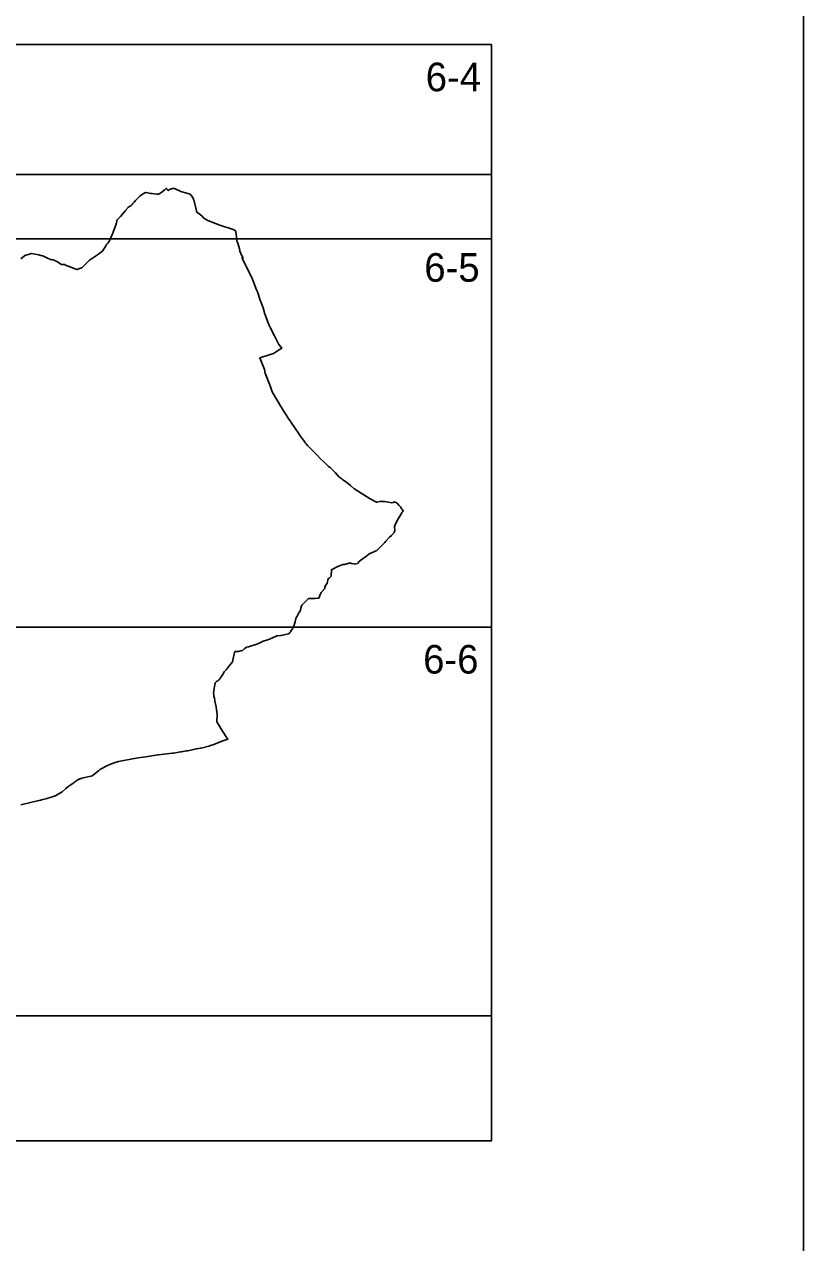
# Model space of a CAD drawing. Extents: x -447352 to -425530, y -1135906 to -1125104.
# Drawn here: x -438259.4 to -438008.8, y -1126663.9 to -1126271.9 of the extents above; entities that cross this region are included whole.
import ezdxf

# ---------------------------------------------------------------- set-up
doc = ezdxf.new("R2010")
doc.units = 0
for name, color, linetype in [('Vrstva 1', 7, 'Continuous'), ('Vrstva 10', 7, 'Continuous'), ('Vrstva 4', 7, 'Continuous')]:
    doc.layers.add(name, color=color, linetype=linetype)

msp = doc.modelspace()

# ---------------------------------------------------------------- linework, layer by layer
at = {"layer": 'Vrstva 1'}
msp.add_lwpolyline([(-439493.8, -1126016.81), (-439493.8, -1127066.81), (-438008.8, -1127066.81), (-438008.8, -1126016.81)], close=True, dxfattribs=at)
msp.add_lwpolyline([(-438260.51, -1126523.09), (-438256.97, -1126522.22), (-438254.2, -1126521.55), (-438253.53, -1126521.34), (-438252.04, -1126520.98), (-438251.83, -1126520.92), (-438250.4, -1126520.53), (-438249.8, -1126520.27), (-438249.58, -1126520.17), (-438249.42, -1126520.11), (-438248.6, -1126519.66), (-438248.54, -1126519.62), (-438247.23, -1126518.84), (-438246.08, -1126517.79), (-438245.43, -1126517.29), (-438245.3, -1126517.18), (-438245.28, -1126517.17), (-438245.12, -1126517.04), (-438244.97, -1126516.94), (-438244.17, -1126516.38), (-438244.11, -1126516.34), (-438244.04, -1126516.29), (-438243.53, -1126515.94), (-438243.16, -1126515.68), (-438242.5, -1126515.22), (-438241.91, -1126514.81), (-438241.75, -1126514.84), (-438241.74, -1126514.84), (-438241.72, -1126514.82), (-438240.99, -1126514.43), (-438238.03, -1126513.85), (-438237.61, -1126513.7), (-438235.58, -1126512.07), (-438235.11, -1126511.73), (-438235.08, -1126511.71), (-438234.72, -1126511.45), (-438234.54, -1126511.33), (-438233.15, -1126510.63), (-438231.74, -1126509.99), (-438231.44, -1126509.84), (-438230.18, -1126509.38), (-438229.18, -1126509.13), (-438223.47, -1126508.07), (-438222.05, -1126507.81), (-438220.34, -1126507.56), (-438216.47, -1126506.99), (-438216.23, -1126506.96), (-438211.93, -1126506.44), (-438211.4, -1126506.38), (-438209.25, -1126506.02), (-438208.93, -1126505.97), (-438207.27, -1126505.7), (-438206.87, -1126505.63), (-438205.46, -1126505.34), (-438204.17, -1126505.07), (-438203.96, -1126505.03), (-438202.79, -1126504.8), (-438202.12, -1126504.67), (-438202.1, -1126504.67), (-438201.19, -1126504.46), (-438201.12, -1126504.44), (-438200.47, -1126504.28), (-438200.12, -1126504.17), (-438199.23, -1126503.88), (-438198.79, -1126503.73), (-438198.14, -1126503.49), (-438198.02, -1126503.45), (-438196.93, -1126502.96), (-438196.93, -1126502.96), (-438196.81, -1126502.92), (-438196.16, -1126502.69), (-438196.07, -1126502.66), (-438195.64, -1126502.5), (-438193.98, -1126501.92), (-438194, -1126501.87), (-438194.11, -1126501.7), (-438194.27, -1126501.47), (-438194.49, -1126501.15), (-438196.19, -1126498.51), (-438196.4, -1126498.16), (-438196.57, -1126497.89), (-438197.01, -1126497.18), (-438197.54, -1126496.33), (-438197.38, -1126493.97), (-438197.37, -1126493.88), (-438197.76, -1126491.58), (-438197.76, -1126491.56), (-438197.77, -1126491.54), (-438197.77, -1126491.54), (-438197.77, -1126491.51), (-438198.18, -1126489.68), (-438198.19, -1126489.49), (-438198.25, -1126488.69), (-438198.35, -1126488.41), (-438198.36, -1126488.39), (-438198.47, -1126488.17), (-438198.51, -1126488.09), (-438198.52, -1126487.71), (-438198.55, -1126487.01), (-438198.5, -1126486.52), (-438198.5, -1126486.5), (-438198.41, -1126485.64), (-438198.39, -1126485.53), (-438198.1, -1126483.89), (-438198.02, -1126483.81), (-438197.72, -1126483.47), (-438197.66, -1126483.4), (-438197.4, -1126483.28), (-438197.34, -1126483.22), (-438197.08, -1126483.02), (-438196.85, -1126482.84), (-438196.64, -1126482.68), (-438196.58, -1126482.64), (-438196.5, -1126482.51), (-438196.42, -1126482.39), (-438196.31, -1126482.22), (-438196.09, -1126481.89), (-438195.67, -1126481.24), (-438195.54, -1126480.99), (-438195.53, -1126480.98), (-438195.39, -1126480.69), (-438195.34, -1126480.6), (-438195.16, -1126480.27), (-438195.02, -1126480.12), (-438194.72, -1126479.81), (-438194.55, -1126479.63), (-438194.27, -1126479.28), (-438194.14, -1126479.11), (-438193.45, -1126478.26), (-438192.79, -1126477.45), (-438192.5, -1126477.09), (-438192.26, -1126475.92), (-438192.2, -1126475.69), (-438192.13, -1126475.41), (-438191.81, -1126474.1), (-438191.73, -1126473.82), (-438191.73, -1126473.79), (-438191.71, -1126473.74), (-438191.55, -1126473.73), (-438191.53, -1126473.73), (-438191.29, -1126473.73), (-438190.6, -1126473.71), (-438190.59, -1126473.71), (-438190.56, -1126473.71), (-438189.88, -1126473.53), (-438189.68, -1126473.47), (-438189.26, -1126473.36), (-438189.24, -1126473.35), (-438189.18, -1126473.29), (-438188.88, -1126473.01), (-438188.76, -1126472.93), (-438188.42, -1126472.67), (-438188, -1126472.35), (-438187.93, -1126472.33), (-438187.37, -1126472.17), (-438184.67, -1126471.41), (-438184.08, -1126471.14), (-438183.75, -1126470.98), (-438183.7, -1126470.96), (-438183.6, -1126470.91), (-438183.24, -1126470.73), (-438183.19, -1126470.71), (-438183.16, -1126470.69), (-438183.15, -1126470.69), (-438183.12, -1126470.67), (-438182.81, -1126470.52), (-438182.75, -1126470.48), (-438182.64, -1126470.43), (-438181.56, -1126470.1), (-438181.13, -1126469.92), (-438180.61, -1126469.7), (-438179.6, -1126469.29), (-438178.18, -1126468.66), (-438178.04, -1126468.65), (-438176.91, -1126468.6), (-438174.51, -1126468.04), (-438173.98, -1126467.64), (-438173.91, -1126467.52), (-438173.82, -1126467.34), (-438173.56, -1126466.83), (-438173.21, -1126466.4), (-438173.19, -1126466.37), (-438172.98, -1126466.08), (-438172.87, -1126465.92), (-438172.86, -1126465.91), (-438172.32, -1126464.13), (-438172.31, -1126464.1), (-438172.11, -1126463.15), (-438171.85, -1126462.69), (-438171.66, -1126462.36), (-438171.11, -1126461.24), (-438170.73, -1126460.73), (-438170.7, -1126460.6), (-438170.63, -1126460.3), (-438170.6, -1126460.16), (-438170.54, -1126459.91), (-438170.52, -1126459.81), (-438170.2, -1126458.8), (-438170.19, -1126458.79), (-438169.9, -1126458.51), (-438169.24, -1126457.88), (-438169.19, -1126457.83), (-438168.72, -1126457.35), (-438168.46, -1126457.09), (-438168.36, -1126456.98), (-438167.99, -1126456.66), (-438167.95, -1126456.66), (-438167.94, -1126456.66), (-438167.53, -1126456.65), (-438167.36, -1126456.66), (-438166.73, -1126456.68), (-438166.02, -1126456.68), (-438165.05, -1126456.59), (-438165.02, -1126456.59), (-438164.77, -1126456.56), (-438164.55, -1126456.2), (-438164.5, -1126456.07), (-438164.48, -1126456.02), (-438164.46, -1126455.96), (-438164.1, -1126454.94), (-438163.96, -1126454.77), (-438163.86, -1126454.66), (-438163.82, -1126454.62), (-438163.76, -1126454.54), (-438163.64, -1126454.41), (-438163.37, -1126454.09), (-438163.28, -1126453.99), (-438163.18, -1126453.87), (-438162.84, -1126453.48), (-438162.77, -1126453.09), (-438162.71, -1126452.78), (-438162.64, -1126452.65), (-438162.09, -1126451.73), (-438161.98, -1126451.34), (-438161.79, -1126450.64), (-438161.67, -1126450.35), (-438161.38, -1126450.08), (-438160.83, -1126449.57), (-438160.76, -1126449.51), (-438160.66, -1126447.4), (-438159.64, -1126446.91), (-438159.24, -1126446.7), (-438158.99, -1126446.57), (-438158.7, -1126446.41), (-438158.48, -1126446.33), (-438158.14, -1126446.2), (-438158.09, -1126446.19), (-438157, -1126445.78), (-438156.99, -1126445.78), (-438156.5, -1126445.72), (-438156.42, -1126445.7), (-438155.39, -1126445.44), (-438155.24, -1126445.4), (-438155.15, -1126445.37), (-438154.98, -1126445.32), (-438154.45, -1126445.15), (-438154.45, -1126445.15), (-438154.44, -1126445.16), (-438154.44, -1126445.16), (-438154.41, -1126445.22), (-438154.28, -1126445.44), (-438153.4, -1126445.54), (-438153.2, -1126445.56), (-438152.84, -1126445.6), (-438152.75, -1126445.56), (-438152.32, -1126445.38), (-438151.67, -1126444.67), (-438150.03, -1126443.51), (-438149.94, -1126443.44), (-438149.77, -1126443.33), (-438149.26, -1126442.91), (-438148.51, -1126442.31), (-438147.24, -1126441.74), (-438146.62, -1126441.47), (-438146.08, -1126441.23), (-438146.02, -1126441.2), (-438144.37, -1126439.53), (-438143.53, -1126438.64), (-438143.17, -1126438.26), (-438141.98, -1126436.9), (-438141.38, -1126436.44), (-438141.33, -1126436.4), (-438140.49, -1126435.39), (-438140.29, -1126434.82), (-438140.38, -1126433.49), (-438140.16, -1126433), (-438139.52, -1126431.55), (-438138.06, -1126429.07), (-438138.03, -1126429.02), (-438138.03, -1126429.02), (-438138.01, -1126428.99), (-438137.98, -1126428.95), (-438137.83, -1126428.76), (-438137.57, -1126428.42), (-438137.83, -1126428.12), (-438137.97, -1126427.9), (-438138.44, -1126427.16), (-438138.64, -1126426.97), (-438138.79, -1126426.81), (-438138.98, -1126426.61), (-438139.56, -1126426.04), (-438140.41, -1126425.57), (-438140.86, -1126425.75), (-438141.19, -1126425.87), (-438142.94, -1126425.6), (-438143.55, -1126425.51), (-438143.69, -1126425.5), (-438144.28, -1126425.48), (-438144.66, -1126425.43), (-438144.82, -1126425.4), (-438144.86, -1126425.4), (-438144.89, -1126425.39), (-438144.89, -1126425.39), (-438144.92, -1126425.4), (-438145.02, -1126425.43), (-438145.15, -1126425.46), (-438146.05, -1126425.7), (-438146.12, -1126425.67), (-438148.19, -1126424.63), (-438150.21, -1126423.35), (-438153.12, -1126421.53), (-438153.28, -1126421.39), (-438153.32, -1126421.36), (-438153.41, -1126421.28), (-438154.55, -1126420.35), (-438155.7, -1126419.3), (-438155.81, -1126419.2), (-438157.02, -1126418.44), (-438157.3, -1126418.21), (-438157.93, -1126417.71), (-438158.24, -1126417.47), (-438158.74, -1126416.94), (-438159.46, -1126416.18), (-438159.61, -1126416.02), (-438160.07, -1126415.53), (-438161.04, -1126414.5), (-438161.24, -1126414.39), (-438161.24, -1126414.39), (-438161.42, -1126414.3), (-438161.62, -1126414.2), (-438162.45, -1126413.37), (-438163.08, -1126412.74), (-438164.26, -1126411.57), (-438165.19, -1126410.63), (-438165.35, -1126410.48), (-438165.79, -1126410.03), (-438166.03, -1126409.79), (-438166.12, -1126409.7), (-438166.16, -1126409.66), (-438166.68, -1126409.14), (-438167.32, -1126408.49), (-438167.4, -1126408.41), (-438167.42, -1126408.39), (-438167.57, -1126408.24), (-438168.4, -1126407.4), (-438168.78, -1126406.9), (-438169.06, -1126406.53), (-438169.38, -1126406.1), (-438169.74, -1126405.62), (-438170.69, -1126404.36), (-438171.06, -1126403.82), (-438173.6, -1126400.08), (-438173.77, -1126399.82), (-438174.54, -1126398.63), (-438175.21, -1126397.62), (-438176.05, -1126396.29), (-438176.85, -1126395.02), (-438176.93, -1126394.89), (-438178.02, -1126393.04), (-438179.7, -1126390.19), (-438179.7, -1126390.18), (-438179.7, -1126390.18), (-438179.71, -1126390.18), (-438180.04, -1126389.2), (-438180.49, -1126387.9), (-438180.55, -1126387.7), (-438181.93, -1126384.19), (-438182.22, -1126382.94), (-438183.7, -1126379.26), (-438183.07, -1126379.06), (-438179.35, -1126377.82), (-438177.38, -1126376.6), (-438177.2, -1126376.49), (-438177.14, -1126376.45), (-438176.94, -1126376.33), (-438176.67, -1126376.16), (-438177.59, -1126374.97), (-438179, -1126372.19), (-438179.75, -1126370.72), (-438180.28, -1126369.56), (-438180.3, -1126369.52), (-438180.36, -1126369.39), (-438180.37, -1126369.36), (-438180.39, -1126369.33), (-438180.43, -1126369.24), (-438180.76, -1126368.51), (-438181.08, -1126367.72), (-438181.79, -1126365.95), (-438182.2, -1126364.91), (-438182.35, -1126364.28), (-438182.61, -1126363.15), (-438183.35, -1126361.26), (-438183.55, -1126360.66), (-438184.49, -1126358.03), (-438184.76, -1126357.31), (-438185.95, -1126354.22), (-438186.02, -1126354.04), (-438186.05, -1126353.96), (-438189.4, -1126347.15), (-438189.09, -1126347.01), (-438189.07, -1126347), (-438189.17, -1126346.83), (-438189.25, -1126346.73), (-438189.42, -1126346.5), (-438189.48, -1126346.42), (-438190.09, -1126344.94), (-438190.14, -1126344.65), (-438190.24, -1126344.19), (-438190.25, -1126344.13), (-438190.76, -1126342.29), (-438191.06, -1126341.66), (-438191.07, -1126341.58), (-438191.11, -1126341.22), (-438191.25, -1126340.13), (-438191.53, -1126338.29), (-438191.59, -1126338.27), (-438191.89, -1126338.17), (-438192.27, -1126337.91), (-438192.28, -1126337.91), (-438196.58, -1126336.5), (-438199.37, -1126335.52), (-438200.68, -1126334.9), (-438201.65, -1126334.34), (-438202.37, -1126333.56), (-438204.05, -1126332.29), (-438204.11, -1126331.99), (-438204.69, -1126329.29), (-438204.84, -1126328.75), (-438205.02, -1126328.24), (-438205.07, -1126328.08), (-438205.32, -1126327.56), (-438205.57, -1126327.25), (-438206.15, -1126326.56), (-438206.9, -1126326.35), (-438209.08, -1126325.69), (-438211.17, -1126324.73), (-438211.79, -1126324.73), (-438212.74, -1126325.1), (-438212.87, -1126325.19), (-438212.94, -1126325.24), (-438213.08, -1126325.34), (-438213.12, -1126325.37), (-438213.14, -1126325.35), (-438213.35, -1126325.1), (-438213.6, -1126324.82), (-438213.68, -1126324.72), (-438213.77, -1126324.76), (-438214.28, -1126325.15), (-438214.47, -1126325.3), (-438215.14, -1126325.82), (-438215.89, -1126326.38), (-438216.23, -1126326.6), (-438216.82, -1126326.56), (-438218.3, -1126326.41), (-438218.76, -1126326.32), (-438220.35, -1126326), (-438220.65, -1126326.11), (-438221.21, -1126326.46), (-438221.76, -1126326.78), (-438222.25, -1126327.24), (-438222.78, -1126327.73), (-438223.18, -1126328.12), (-438223.19, -1126328.13), (-438223.52, -1126328.47), (-438223.65, -1126328.61), (-438224.16, -1126329.16), (-438224.61, -1126329.71), (-438224.77, -1126329.9), (-438225.13, -1126330.33), (-438225.87, -1126330.66), (-438225.89, -1126330.66), (-438226.09, -1126330.91), (-438226.95, -1126331.93), (-438227.33, -1126332.38), (-438228.46, -1126333.74), (-438228.47, -1126333.75), (-438229.71, -1126334.92), (-438229.83, -1126335.76), (-438229.88, -1126336.13), (-438229.92, -1126336.23), (-438230.4, -1126337.58), (-438230.84, -1126338.82), (-438230.87, -1126338.9), (-438231.17, -1126339.59), (-438232.1, -1126341.77), (-438232.12, -1126341.78), (-438232.69, -1126342.46), (-438232.99, -1126342.81), (-438232.99, -1126342.82), (-438233.33, -1126343.36), (-438234.2, -1126344.75), (-438234.29, -1126344.89), (-438234.46, -1126345.02), (-438234.99, -1126345.41), (-438235.6, -1126345.86), (-438235.6, -1126345.86), (-438236.57, -1126346.49), (-438236.7, -1126346.58), (-438236.88, -1126346.7), (-438238.18, -1126347.56), (-438238.19, -1126347.57), (-438238.45, -1126347.83), (-438238.57, -1126347.95), (-438238.79, -1126348.18), (-438239.07, -1126348.46), (-438239.64, -1126349.03), (-438240.8, -1126350.19), (-438241, -1126350.27), (-438242.5, -1126350.84), (-438245.31, -1126349.72), (-438245.31, -1126349.73), (-438245.32, -1126349.75), (-438246.23, -1126349.37), (-438246.54, -1126349.24), (-438246.56, -1126349.24), (-438246.95, -1126349.24), (-438247.43, -1126349.24), (-438248.99, -1126348.25), (-438249.25, -1126348.12), (-438249.54, -1126347.96), (-438249.6, -1126347.93), (-438249.64, -1126347.91), (-438250.18, -1126347.68), (-438250.23, -1126347.68), (-438250.24, -1126347.68), (-438250.39, -1126347.67), (-438250.51, -1126347.66), (-438250.82, -1126347.64), (-438250.84, -1126347.64), (-438250.84, -1126347.64), (-438250.95, -1126347.6), (-438251.19, -1126347.5), (-438251.79, -1126347.25), (-438251.95, -1126347.18), (-438253.47, -1126346.45), (-438254.09, -1126346.27), (-438254.76, -1126346.07), (-438257.08, -1126345.64), (-438257.09, -1126345.64), (-438257.49, -1126345.75), (-438259.23, -1126346.33), (-438259.36, -1126346.44), (-438260.57, -1126347.4)], dxfattribs=at)
at = {"layer": 'Vrstva 10'}
msp.add_lwpolyline([(-438109.21, -1126320.23), (-438109.21, -1126631.21), (-438442.08, -1126631.21), (-438442.08, -1126465.91), (-438421.71, -1126465.91), (-438421.71, -1126340.91), (-438421.71, -1126320.23), (-438109.21, -1126320.23)], dxfattribs=at)
at = {"layer": 'Vrstva 4'}
msp.add_line((-438421.71, -1126278.41), (-438109.21, -1126278.41), dxfattribs=at)
msp.add_lwpolyline([(-438109.21, -1126278.41), (-438109.21, -1126340.91), (-438265.46, -1126340.91), (-438265.46, -1126278.41)], dxfattribs=at)
for points in [[(-438109.21, -1126340.91), (-438109.21, -1126465.91), (-438265.46, -1126465.91), (-438265.46, -1126340.91)], [(-438109.21, -1126465.91), (-438109.21, -1126590.91), (-438265.46, -1126590.91), (-438265.46, -1126465.91)]]:
    msp.add_lwpolyline(points, close=True, dxfattribs=at)

# ---------------------------------------------------------------- texts
at = {"layer": 'Vrstva 1'}
for s, p in [('6-4', (-438130.34, -1126293.46)), ('6-5', (-438130.79, -1126354.75)), ('6-6', (-438131.16, -1126480.82))]:
    msp.add_text(s, height=9.2, dxfattribs=at).set_placement(p)

doc.saveas('drawing.dxf')
